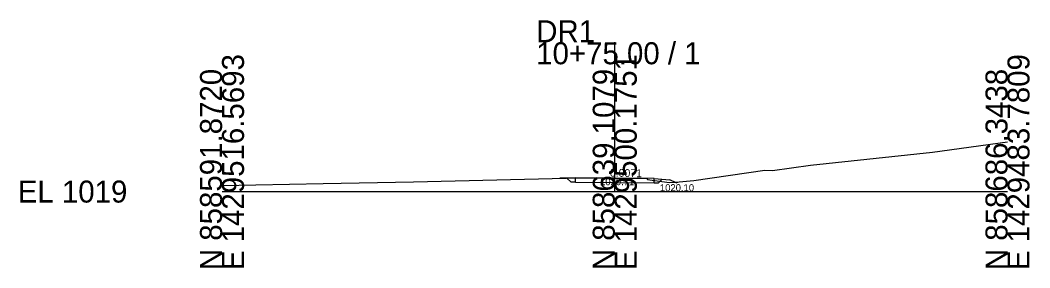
# Model space of a CAD drawing. Extents: x -26 to 103, y -10 to 1022.
# Drawn here: x -25.7 to 102.8, y 990.3 to 1021.8 of the extents above; entities that cross this region are included whole.
import ezdxf

# ---------------------------------------------------------------- set-up
doc = ezdxf.new("R2010")
doc.units = 0
for name, color, linetype in [('Default', 7, 'Continuous'), ('Exist Cross Section Cell', 7, 'Continuous'), ('Exist XS Center Line Elevation Label', 7, 'Continuous'), ('Exist XS Ground Line', 7, 'Continuous'), ('Prop CMT Pvmt Surface', 7, 'Continuous'), ('Prop CMT Shld Paved Course 1', 7, 'Continuous'), ('Prop CMT Slope Grass', 7, 'Continuous'), ('Prop CMT Subgrade Earthwork', 7, 'Continuous'), ('Prop CMT Template Flag', 7, 'Continuous'), ('Prop XS SE Text', 7, 'Continuous')]:
    doc.layers.add(name, color=color, linetype=linetype)

msp = doc.modelspace()

# ---------------------------------------------------------------- linework, layer by layer
at = {"layer": 'Exist Cross Section Cell'}
for p, q in [((50, 1000), (50, 1018.99)), ((0, 1000), (50, 1000)), ((50, 1000), (100, 1000))]:
    msp.add_line(p, q, dxfattribs=at)
at = {"layer": 'Exist XS Ground Line'}
msp.add_lwpolyline([(0, 1000.77), (12.88, 1001.03), (24.39, 1001.25), (43.83, 1001.71), (45, 1001.74), (50, 1001.71), (54.09, 1001.68), (54.16, 1001.52), (56.91, 1001.15), (57.75, 1001.18), (60.05, 1001.41), (69.11, 1002.72), (70.1, 1002.68), (74.92, 1003.34), (90.44, 1005.02), (100, 1006.33)], dxfattribs=at)
at = {"layer": 'Prop CMT Pvmt Surface'}
msp.add_line((55, 1001.67), (50, 1001.71), dxfattribs=at)
msp.add_lwpolyline([(50, 1001.71), (45, 1001.74)], dxfattribs=at)
at = {"layer": 'Prop CMT Shld Paved Course 1'}
for points in [[(45, 1001.2), (45, 1001.74)], [(55, 1001.13), (55, 1001.67)]]:
    msp.add_lwpolyline(points, dxfattribs=at)
at = {"layer": 'Prop CMT Slope Grass'}
for q in [(57, 1001.51), (58.04, 1001.21)]:
    msp.add_line((57.82, 1001.1), q, dxfattribs=at)
for points in [[(45, 1001.74), (43, 1001.69)], [(55, 1001.67), (57, 1001.51)]]:
    msp.add_lwpolyline(points, dxfattribs=at)
at = {"layer": 'Prop CMT Subgrade Earthwork'}
for points in [[(44.45, 1001.19), (43.92, 1001.72)], [(55.55, 1001.12), (56.03, 1001.59)], [(45, 1001.2), (44.45, 1001.19)], [(55, 1001.13), (55.55, 1001.12)]]:
    msp.add_lwpolyline(points, dxfattribs=at)
at = {"layer": 'Prop CMT Template Flag'}
for points in [[(45, 1001.2), (50, 1001.16)], [(50, 1001.16), (55, 1001.13)]]:
    msp.add_lwpolyline(points, dxfattribs=at)

# ---------------------------------------------------------------- texts
at = {"layer": 'Default'}
msp.add_text('1020.10', height=0.9, dxfattribs=at).set_placement((55.75, 1000.04))
at = {"layer": 'Exist Cross Section Cell'}
for s, p in [('DR1', (40, 1018.99)), ('10+75.00 / 1', (40, 1016.19)), ('EL 1019', (-26, 998.6))]:
    msp.add_text(s, height=2.8, dxfattribs=at).set_placement(p)
for s, p in [('E 1429516.5693', (2.8, 990)), ('E 1429500.1751', (52.8, 990)), ('E 1429483.7809', (102.8, 990)), ('N 858591.8720', (0, 990)), ('N 858639.1079', (50, 990)), ('N 858686.3438', (100, 990))]:
    msp.add_text(s, height=2.8, rotation=90, dxfattribs=at).set_placement(p)
at = {"layer": 'Exist XS Center Line Elevation Label'}
msp.add_text('1020.71', height=0.9, dxfattribs=at).set_placement((48.13, 1000.81))
at = {"layer": 'Prop XS SE Text'}
msp.add_text('0.0071', height=1, rotation=358.8542, dxfattribs=at).set_placement((49.37, 1001.9))

doc.saveas('drawing.dxf')
